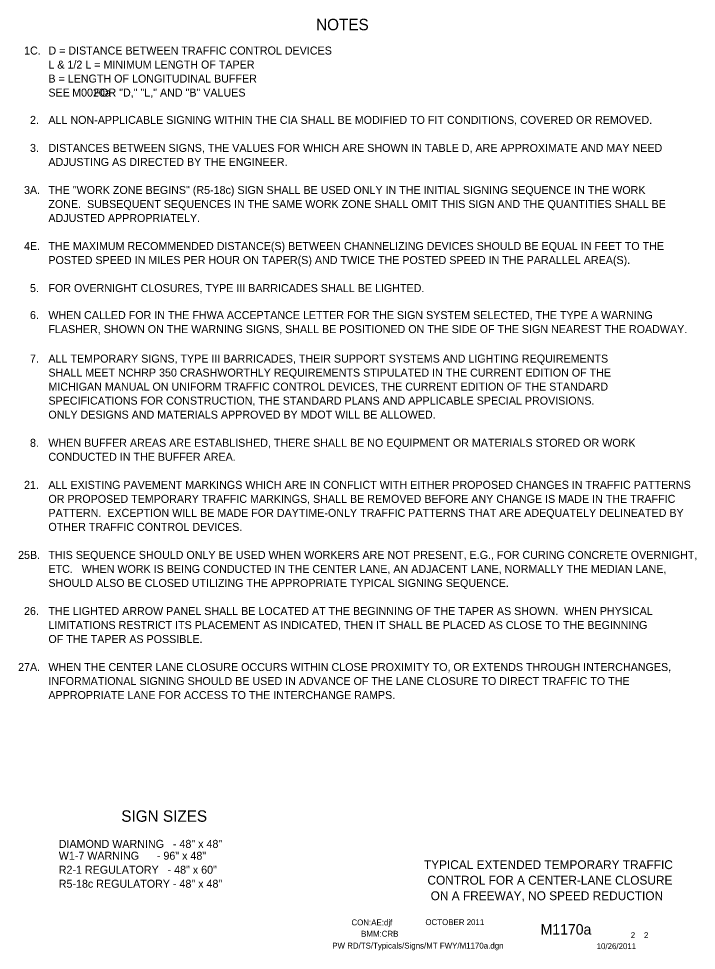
# Model space of a CAD drawing. Extents: x 16450 to 18482, y 7002 to 8333.
# Drawn here: x 17770 to 18482, y 7218 to 8195 of the extents above; entities that cross this region are included whole.
import ezdxf

# ---------------------------------------------------------------- set-up
doc = ezdxf.new("R2010")
doc.units = 0
for name, color, linetype in [('BORDER', 7, 'Continuous'), ('BORDER_SIGNAL_WO', 7, 'Continuous'), ('TYPICAL_TEXT_DIMEN_PR', 7, 'Continuous')]:
    doc.layers.add(name, color=color, linetype=linetype)

msp = doc.modelspace()

# ---------------------------------------------------------------- linework, layer by layer
at = {"layer": 'BORDER'}
msp.add_line((18317.58, 7297.26), (18317.58, 7297.26), dxfattribs=at)

# ---------------------------------------------------------------- texts
for s, p in [('TYPICAL EXTENDED TEMPORARY TRAFFIC', (18195.71, 7303.33)), ('CONTROL FOR A CENTER-LANE CLOSURE', (18199.4, 7287.03)), ('ON A FREEWAY, NO SPEED REDUCTION', (18202.8, 7270.73))]:
    msp.add_text(s, height=9.3, dxfattribs=at).set_placement(p)
at = {"layer": 'BORDER_SIGNAL_WO'}
for s, height, p in [('CON:AE:djf  ', 6.2, (18119.69, 7244.31)), ('    OCTOBER 2011    ', 6.2, (18188.08, 7244.59)), ('    M1170a   ', 11, (18301.86, 7234.63)), ('BMM:CRB   ', 6.2, (18129.81, 7232.42)), (' 2    2 ', 6.2, (18410.45, 7230.95)), ('PW RD/TS/Typicals/Signs/MT FWY/M1170a.dgn      ', 6.2, (18099.55, 7219.96)), ('10/26/2011    ', 6.2, (18376.93, 7219.38))]:
    msp.add_text(s, height=height, dxfattribs=at).set_placement(p)
at = {"layer": 'TYPICAL_TEXT_DIMEN_PR'}
for s, height, p in [('NOTES', 12, (18082.55, 8183.25)), ('1C.', 8.4, (17776.19, 8157.75)), ('D = DISTANCE BETWEEN TRAFFIC CONTROL DEVICES', 8.4, (17801.7, 8157.75)), ('L & 1/2 L = MINIMUM LENGTH OF TAPER', 8.4, (17801.7, 8143.05)), ('B = LENGTH OF LONGITUDINAL BUFFER', 8.4, (17801.7, 8128.35)), ('SEE        FOR "D," "L," AND "B" VALUES', 8.4, (17801.7, 8113.65)), ('M0020a', 8.4, (17826.62, 8113.65)), ('2.', 8.4, (17782.39, 8085)), ('ALL NON-APPLICABLE SIGNING WITHIN THE CIA SHALL BE MODIFIED TO FIT CONDITIONS, COVERED OR REMOVED.', 8.4, (17801.7, 8085)), ('3.', 8.4, (17782.39, 8055.6)), ('DISTANCES BETWEEN SIGNS, THE VALUES FOR WHICH ARE SHOWN IN TABLE D, ARE APPROXIMATE AND MAY NEED', 8.4, (17801.7, 8055.6)), ('ADJUSTING AS DIRECTED BY THE ENGINEER.', 8.4, (17801.7, 8040.9)), ('3A.', 8.4, (17776.09, 8011.49)), ('THE "WORK ZONE BEGINS" (R5-18c) SIGN SHALL BE USED ONLY IN THE INITIAL SIGNING SEQUENCE IN THE WORK', 8.4, (17801.7, 8011.49)), ('ZONE.  SUBSEQUENT SEQUENCES IN THE SAME WORK ZONE SHALL OMIT THIS SIGN AND THE QUANTITIES SHALL BE', 8.4, (17801.7, 7996.79)), ('ADJUSTED APPROPRIATELY.', 8.4, (17801.7, 7982.09)), ('4E.', 8.4, (17776.13, 7952.7)), ('THE MAXIMUM RECOMMENDED DISTANCE(S) BETWEEN CHANNELIZING DEVICES SHOULD BE EQUAL IN FEET TO THE', 8.4, (17801.7, 7952.7)), ('POSTED SPEED IN MILES PER HOUR ON TAPER(S) AND TWICE THE POSTED SPEED IN THE PARALLEL AREA(S).', 8.4, (17801.7, 7938)), ('5.', 8.4, (17782.39, 7908.6)), ('FOR OVERNIGHT CLOSURES, TYPE III BARRICADES SHALL BE LIGHTED. ', 8.4, (17801.7, 7908.6)), ('6.', 8.4, (17782.34, 7880.29)), ('WHEN CALLED FOR IN THE FHWA ACCEPTANCE LETTER FOR THE SIGN SYSTEM SELECTED, THE TYPE A WARNING ', 8.4, (17801.7, 7880.29)), ('FLASHER, SHOWN ON THE WARNING SIGNS, SHALL BE POSITIONED ON THE SIDE OF THE SIGN NEAREST THE ROADWAY.', 8.4, (17801.7, 7865.59)), ('7.', 8.4, (17782.34, 7834.62)), ('ALL TEMPORARY SIGNS, TYPE III BARRICADES, THEIR SUPPORT SYSTEMS AND LIGHTING REQUIREMENTS', 8.4, (17801.7, 7834.64)), ('SHALL MEET NCHRP 350 CRASHWORTHLY REQUIREMENTS STIPULATED IN THE CURRENT EDITION OF THE', 8.4, (17801.7, 7819.94)), ('MICHIGAN MANUAL ON UNIFORM TRAFFIC CONTROL DEVICES, THE CURRENT EDITION OF THE STANDARD', 8.4, (17801.7, 7805.24)), ('SPECIFICATIONS FOR CONSTRUCTION, THE STANDARD PLANS AND APPLICABLE SPECIAL PROVISIONS.', 8.4, (17801.7, 7790.54)), ('ONLY DESIGNS AND MATERIALS APPROVED BY MDOT WILL BE ALLOWED.', 8.4, (17801.7, 7775.84)), ('8.', 8.4, (17782.39, 7746.3)), ('WHEN BUFFER AREAS ARE ESTABLISHED, THERE SHALL BE NO EQUIPMENT OR MATERIALS STORED OR WORK     ', 8.4, (17801.7, 7746.3)), ('CONDUCTED IN THE BUFFER AREA.', 8.4, (17801.7, 7731.6)), ('21.', 8.4, (17776.14, 7702.19)), ('ALL EXISTING PAVEMENT MARKINGS WHICH ARE IN CONFLICT WITH EITHER PROPOSED CHANGES IN TRAFFIC PATTERNS', 8.4, (17801.7, 7702.19)), ('OR PROPOSED TEMPORARY TRAFFIC MARKINGS, SHALL BE REMOVED BEFORE ANY CHANGE IS MADE IN THE TRAFFIC', 8.4, (17801.7, 7687.49)), ('PATTERN.  EXCEPTION WILL BE MADE FOR DAYTIME-ONLY TRAFFIC PATTERNS THAT ARE ADEQUATELY DELINEATED BY', 8.4, (17801.7, 7672.8)), ('OTHER TRAFFIC CONTROL DEVICES.', 8.4, (17801.7, 7658.1)), ('25B.', 8.4, (17769.88, 7628.69)), ('THIS SEQUENCE SHOULD ONLY BE USED WHEN WORKERS ARE NOT PRESENT, E.G., FOR CURING CONCRETE OVERNIGHT,', 8.4, (17801.7, 7628.69)), ('ETC.   WHEN WORK IS BEING CONDUCTED IN THE CENTER LANE, AN ADJACENT LANE, NORMALLY THE MEDIAN LANE,', 8.4, (17801.7, 7613.99)), ('SHOULD ALSO BE CLOSED UTILIZING THE APPROPRIATE TYPICAL SIGNING SEQUENCE.', 8.4, (17801.7, 7599.3)), ('26.', 8.4, (17776.09, 7569.9)), ('THE LIGHTED ARROW PANEL SHALL BE LOCATED AT THE BEGINNING OF THE TAPER AS SHOWN.  WHEN PHYSICAL', 8.4, (17801.7, 7569.9)), ('LIMITATIONS RESTRICT ITS PLACEMENT AS INDICATED, THEN IT SHALL BE PLACED AS CLOSE TO THE BEGINNING', 8.4, (17801.7, 7555.19)), ('OF THE TAPER AS POSSIBLE.', 8.4, (17801.7, 7540.49)), ('27A.', 8.4, (17769.88, 7511.1)), ('WHEN THE CENTER LANE CLOSURE OCCURS WITHIN CLOSE PROXIMITY TO, OR EXTENDS THROUGH INTERCHANGES,', 8.4, (17801.7, 7511.1)), ('INFORMATIONAL SIGNING SHOULD BE USED IN ADVANCE OF THE LANE CLOSURE TO DIRECT TRAFFIC TO THE', 8.4, (17801.7, 7496.4)), ('APPROPRIATE LANE FOR ACCESS TO THE INTERCHANGE RAMPS.', 8.4, (17801.7, 7481.69)), ('SIGN SIZES', 12, (17878.15, 7352.98)), ('DIAMOND WARNING   - 48" x 48"', 8.4, (17812.55, 7325.58)), ('W1-7 WARNING      - 96" x 48"', 8.4, (17812.55, 7313.18)), ('R2-1 REGULATORY   - 48" x 60"', 8.4, (17812.55, 7298.48)), ('R5-18c REGULATORY - 48" x 48"', 8.4, (17812.55, 7283.78))]:
    msp.add_text(s, height=height, dxfattribs=at).set_placement(p)

doc.saveas('drawing.dxf')
